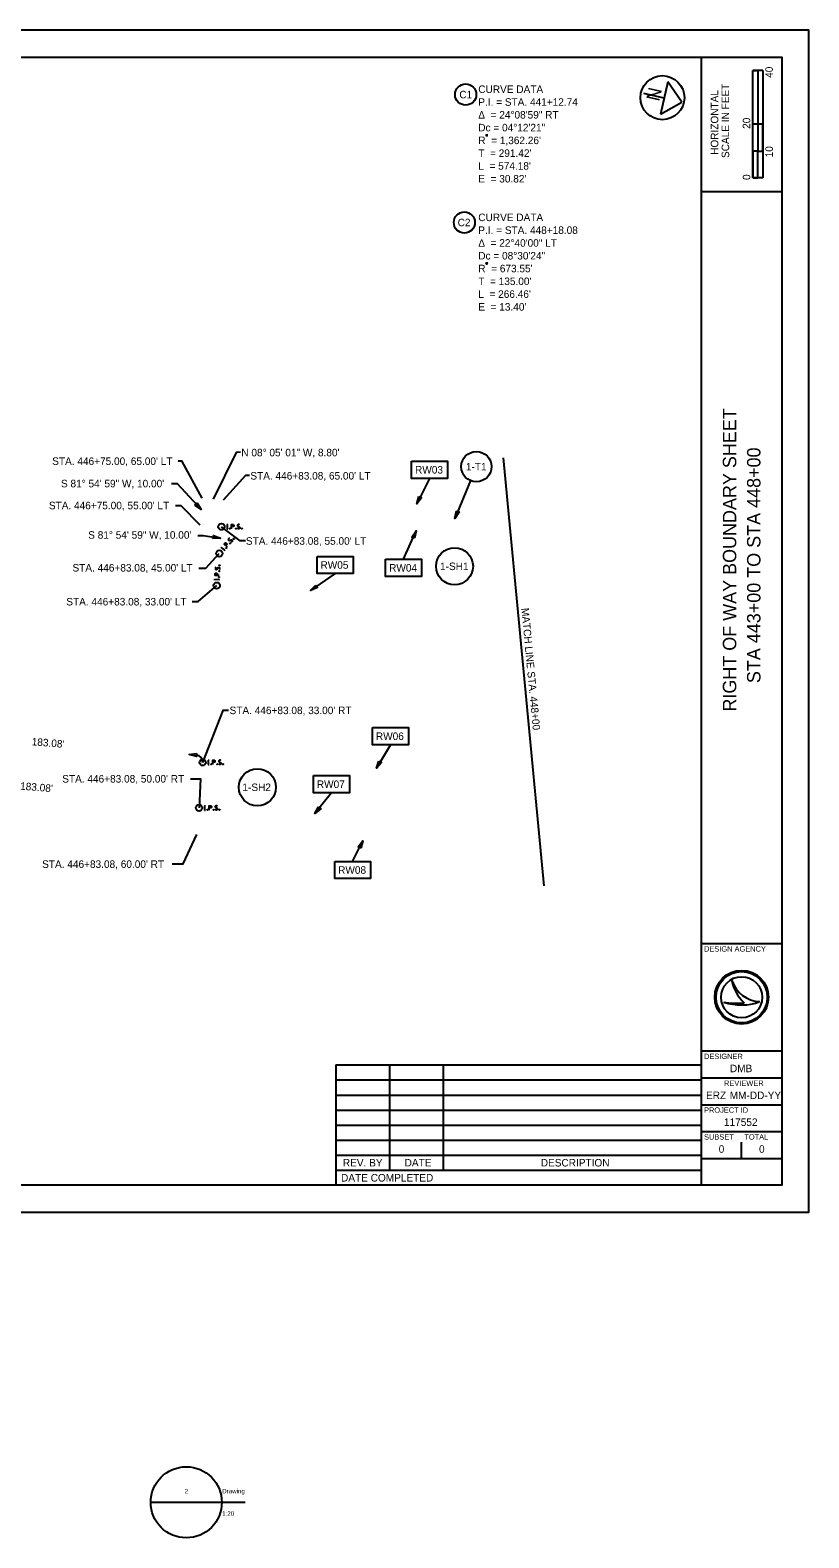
# Model space of a CAD drawing. Extents: x 0 to 1181, y -186 to 440.
# Drawn here: x 390 to 680, y -121 to 440 of the extents above; entities that cross this region are included whole.
import ezdxf

# ---------------------------------------------------------------- set-up
doc = ezdxf.new("R2010")
doc.units = 0
for name, color, linetype in [('RW_X_CL_100_Bearings', 7, 'Continuous'), ('RW_X_CL_100_Curve_Data', 7, 'Continuous'), ('SH_Border', 7, 'Continuous'), ('SH_Cut_Line', 7, 'Continuous'), ('SH_Data', 7, 'Continuous'), ('SH_Masking', 7, 'Continuous'), ('SH_Text', 7, 'Continuous'), ('SV_X_Shot_Marker', 7, 'Continuous')]:
    doc.layers.add(name, color=color, linetype=linetype)

msp = doc.modelspace()

# ---------------------------------------------------------------- linework, layer by layer
at = {"layer": 'RW_X_CL_100_Bearings'}
for points in [[(463.44, 255.96), (463.79, 255.96)], [(463.44, 254.36), (463.79, 254.36)], [(463.62, 254.36), (463.62, 255.96)], [(464.58, 254.57), (464.63, 254.57), (464.66, 254.55), (464.7, 254.5), (464.7, 254.43), (464.66, 254.38), (464.63, 254.36), (464.58, 254.36), (464.54, 254.38), (464.51, 254.43), (464.51, 254.5), (464.54, 254.55), (464.58, 254.57)], [(465.18, 254.36), (465.18, 255.96), (465.71, 255.96), (465.77, 255.94), (465.84, 255.92), (465.88, 255.89), (465.91, 255.87), (465.95, 255.81), (465.99, 255.74), (466.01, 255.64), (466.01, 255.49), (466, 255.44), (465.98, 255.36), (465.93, 255.28), (465.89, 255.24), (465.85, 255.21), (465.8, 255.19), (465.71, 255.18), (465.18, 255.18)], [(466.82, 254.57), (466.88, 254.57), (466.91, 254.55), (466.95, 254.5), (466.95, 254.43), (466.91, 254.38), (466.88, 254.36), (466.82, 254.36), (466.79, 254.38), (466.76, 254.43), (466.76, 254.5), (466.79, 254.55), (466.82, 254.57)], [(468.19, 255.84), (468.17, 255.87), (468.14, 255.89), (468.04, 255.93), (467.92, 255.96), (467.83, 255.96), (467.79, 255.96), (467.65, 255.92), (467.53, 255.84), (467.45, 255.74), (467.43, 255.64), (467.43, 255.57), (467.45, 255.47), (467.54, 255.38), (468.15, 255), (468.2, 254.95), (468.22, 254.9), (468.25, 254.82), (468.25, 254.75), (468.24, 254.67), (468.22, 254.62), (468.2, 254.56), (468.18, 254.51), (468.16, 254.47), (468.12, 254.43), (468.09, 254.41), (468.05, 254.38), (468.01, 254.37), (467.92, 254.36), (467.76, 254.36), (467.66, 254.38), (467.52, 254.47), (467.43, 254.55)], [(469.01, 254.57), (469.06, 254.57), (469.09, 254.55), (469.13, 254.5), (469.13, 254.43), (469.09, 254.38), (469.06, 254.36), (469.01, 254.36), (468.97, 254.38), (468.94, 254.43), (468.94, 254.5), (468.97, 254.55), (469.01, 254.57)], [(461.29, 247.26), (461.52, 247.53)], [(462.64, 246.37), (461.4, 247.39)], [(463.63, 247.58), (462.4, 248.6), (462.73, 249.01), (462.78, 249.04), (462.85, 249.09), (462.89, 249.1), (462.93, 249.11), (463.01, 249.1), (463.08, 249.08), (463.17, 249.04), (463.28, 248.94), (463.32, 248.9), (463.36, 248.84), (463.4, 248.75), (463.4, 248.69), (463.4, 248.65), (463.38, 248.59), (463.34, 248.51), (463, 248.1)], [(463.08, 247.25), (463.12, 247.29), (463.16, 247.3), (463.22, 247.3), (463.27, 247.26), (463.28, 247.2), (463.28, 247.16), (463.25, 247.11), (463.21, 247.11), (463.15, 247.11), (463.1, 247.15), (463.08, 247.21), (463.08, 247.25)], [(464.4, 250.85), (464.37, 250.85), (464.32, 250.84), (464.23, 250.79), (464.14, 250.71), (464.08, 250.64), (464.06, 250.62), (464, 250.48), (463.98, 250.34), (464.01, 250.22), (464.07, 250.14), (464.13, 250.09), (464.22, 250.04), (464.35, 250.05), (465.02, 250.28), (465.1, 250.29), (465.15, 250.28), (465.22, 250.24), (465.28, 250.2), (465.33, 250.14), (465.36, 250.1), (465.4, 250.04), (465.42, 249.99), (465.44, 249.95), (465.45, 249.9), (465.44, 249.86), (465.44, 249.81), (465.42, 249.78), (465.37, 249.69), (465.27, 249.57), (465.19, 249.51), (465.03, 249.46), (464.92, 249.44)], [(464.51, 248.99), (464.55, 249.03), (464.59, 249.04), (464.65, 249.03), (464.7, 248.99), (464.71, 248.93), (464.71, 248.89), (464.68, 248.85), (464.64, 248.84), (464.58, 248.85), (464.53, 248.89), (464.51, 248.95), (464.51, 248.99)], [(465.9, 250.67), (465.93, 250.71), (465.97, 250.72), (466.03, 250.72), (466.08, 250.68), (466.1, 250.62), (466.1, 250.58), (466.06, 250.54), (466.02, 250.53), (465.96, 250.53), (465.92, 250.57), (465.9, 250.63), (465.9, 250.67)], [(462.53, 246.24), (462.75, 246.51)], [(460.63, 236.95), (459.04, 237.02), (459.06, 237.55), (459.07, 237.6), (459.1, 237.68), (459.13, 237.71), (459.16, 237.74), (459.22, 237.78), (459.29, 237.81), (459.39, 237.83), (459.54, 237.82), (459.59, 237.81), (459.66, 237.78), (459.75, 237.74), (459.78, 237.69), (459.81, 237.66), (459.83, 237.6), (459.84, 237.51), (459.82, 236.98)], [(459.28, 240.02), (459.25, 240), (459.23, 239.97), (459.19, 239.87), (459.15, 239.75), (459.15, 239.66), (459.15, 239.63), (459.18, 239.48), (459.25, 239.36), (459.35, 239.28), (459.45, 239.25), (459.52, 239.25), (459.63, 239.26), (459.72, 239.35), (460.12, 239.94), (460.17, 239.99), (460.23, 240.01), (460.3, 240.03), (460.38, 240.03), (460.45, 240.01), (460.5, 240), (460.56, 239.97), (460.61, 239.95), (460.65, 239.93), (460.69, 239.89), (460.71, 239.86), (460.73, 239.81), (460.75, 239.78), (460.75, 239.68), (460.75, 239.52), (460.72, 239.43), (460.62, 239.29), (460.54, 239.2)], [(460.39, 236.35), (460.4, 236.41), (460.42, 236.44), (460.47, 236.47), (460.54, 236.47), (460.59, 236.43), (460.61, 236.4), (460.61, 236.34), (460.58, 236.31), (460.53, 236.28), (460.47, 236.28), (460.42, 236.32), (460.39, 236.35)], [(460.49, 238.6), (460.49, 238.65), (460.52, 238.68), (460.57, 238.72), (460.64, 238.71), (460.68, 238.68), (460.71, 238.64), (460.71, 238.59), (460.68, 238.56), (460.63, 238.53), (460.56, 238.53), (460.52, 238.56), (460.49, 238.6)], [(460.59, 240.78), (460.59, 240.83), (460.62, 240.87), (460.67, 240.9), (460.73, 240.89), (460.78, 240.86), (460.8, 240.82), (460.8, 240.77), (460.77, 240.74), (460.72, 240.71), (460.66, 240.71), (460.61, 240.74), (460.59, 240.78)], [(458.96, 235.28), (458.98, 235.63)], [(460.57, 235.38), (458.97, 235.45)], [(460.56, 235.21), (460.57, 235.56)], [(456.45, 168.24), (456.8, 168.24)], [(456.45, 166.64), (456.8, 166.64)], [(456.63, 166.64), (456.63, 168.24)], [(457.58, 166.85), (457.64, 166.85), (457.67, 166.82), (457.71, 166.77), (457.71, 166.71), (457.67, 166.66), (457.64, 166.64), (457.58, 166.64), (457.55, 166.66), (457.52, 166.71), (457.52, 166.77), (457.55, 166.82), (457.58, 166.85)], [(458.19, 166.64), (458.19, 168.24), (458.72, 168.24), (458.78, 168.22), (458.85, 168.2), (458.89, 168.17), (458.92, 168.15), (458.96, 168.08), (459, 168.02), (459.02, 167.92), (459.02, 167.77), (459.01, 167.72), (458.98, 167.64), (458.94, 167.55), (458.9, 167.52), (458.86, 167.49), (458.81, 167.47), (458.72, 167.45), (458.19, 167.45)], [(459.83, 166.85), (459.89, 166.85), (459.92, 166.82), (459.95, 166.77), (459.95, 166.71), (459.92, 166.66), (459.89, 166.64), (459.83, 166.64), (459.8, 166.66), (459.77, 166.71), (459.77, 166.77), (459.8, 166.82), (459.83, 166.85)], [(461.2, 168.12), (461.18, 168.15), (461.15, 168.17), (461.05, 168.21), (460.92, 168.24), (460.84, 168.24), (460.8, 168.24), (460.66, 168.2), (460.54, 168.12), (460.46, 168.02), (460.44, 167.92), (460.44, 167.84), (460.46, 167.74), (460.55, 167.66), (461.16, 167.28), (461.21, 167.23), (461.23, 167.18), (461.26, 167.1), (461.26, 167.03), (461.24, 166.95), (461.23, 166.9), (461.21, 166.84), (461.19, 166.79), (461.17, 166.75), (461.13, 166.71), (461.1, 166.69), (461.06, 166.66), (461.02, 166.65), (460.92, 166.64), (460.77, 166.64), (460.67, 166.66), (460.53, 166.75), (460.44, 166.82)], [(462.02, 166.85), (462.07, 166.85), (462.1, 166.82), (462.14, 166.77), (462.14, 166.71), (462.1, 166.66), (462.07, 166.64), (462.02, 166.64), (461.98, 166.66), (461.95, 166.71), (461.95, 166.77), (461.98, 166.82), (462.02, 166.85)], [(455.1, 151.29), (455.45, 151.29)], [(455.1, 149.69), (455.45, 149.69)], [(455.28, 149.69), (455.28, 151.29)], [(456.23, 149.9), (456.29, 149.9), (456.32, 149.88), (456.36, 149.83), (456.36, 149.76), (456.32, 149.71), (456.29, 149.69), (456.23, 149.69), (456.2, 149.71), (456.17, 149.76), (456.17, 149.83), (456.2, 149.88), (456.23, 149.9)], [(456.84, 149.69), (456.84, 151.29), (457.37, 151.29), (457.42, 151.28), (457.5, 151.25), (457.54, 151.23), (457.57, 151.2), (457.61, 151.14), (457.65, 151.07), (457.67, 150.97), (457.67, 150.82), (457.66, 150.77), (457.63, 150.7), (457.59, 150.61), (457.55, 150.57), (457.51, 150.55), (457.46, 150.52), (457.37, 150.51), (456.84, 150.51)], [(458.48, 149.9), (458.54, 149.9), (458.57, 149.88), (458.6, 149.83), (458.6, 149.76), (458.57, 149.71), (458.54, 149.69), (458.48, 149.69), (458.45, 149.71), (458.42, 149.76), (458.42, 149.83), (458.45, 149.88), (458.48, 149.9)], [(459.85, 151.18), (459.83, 151.2), (459.79, 151.23), (459.7, 151.26), (459.57, 151.29), (459.49, 151.29), (459.45, 151.29), (459.31, 151.25), (459.19, 151.18), (459.11, 151.07), (459.09, 150.97), (459.09, 150.9), (459.11, 150.8), (459.2, 150.71), (459.81, 150.33), (459.86, 150.28), (459.88, 150.23), (459.9, 150.16), (459.9, 150.08), (459.89, 150), (459.88, 149.95), (459.86, 149.89), (459.84, 149.84), (459.82, 149.8), (459.78, 149.76), (459.75, 149.74), (459.71, 149.71), (459.67, 149.7), (459.57, 149.69), (459.42, 149.69), (459.32, 149.71), (459.18, 149.8), (459.09, 149.88)], [(460.67, 149.9), (460.72, 149.9), (460.75, 149.88), (460.79, 149.83), (460.79, 149.76), (460.75, 149.71), (460.72, 149.69), (460.67, 149.69), (460.63, 149.71), (460.6, 149.76), (460.6, 149.83), (460.63, 149.88), (460.67, 149.9)]]:
    msp.add_lwpolyline(points, dxfattribs=at)
for centre in [(461.42, 255.16), (460.63, 245.19), (459.67, 233.23), (454.43, 167.43), (453.08, 150.49)]:
    msp.add_circle(centre, 1.2, dxfattribs=at)
at = {"layer": 'SH_Border'}
for p, q in [((640, 10), (640, 430)), ((640, 380), (670, 380)), ((640, 100), (670, 100)), ((640, 60), (670, 60)), ((640, 50), (670, 50)), ((640, 40), (670, 40)), ((640, 30), (670, 30)), ((640, 20), (670, 20))]:
    msp.add_line(p, q, dxfattribs=at)
msp.add_lwpolyline([(30, 430), (670, 430), (670, 10), (30, 10)], close=True, dxfattribs=at)
at = {"layer": 'SH_Cut_Line'}
msp.add_lwpolyline([(0, 0), (680, 0), (680, 440), (0, 440)], close=True, dxfattribs=at)
at = {"layer": 'SH_Data'}
for p, q in [((659.13, 385), (659.13, 425)), ((662.88, 425), (659.13, 425)), ((659.13, 405), (659.13, 425)), ((659.13, 425), (661, 425)), ((661, 425), (661.02, 425)), ((661.02, 425), (661.02, 405)), ((662.88, 425), (662.88, 385)), ((661.02, 405), (659.13, 405)), ((662.87, 405), (661, 405)), ((661, 405), (661, 395)), ((662.87, 395), (662.87, 405)), ((661, 395), (659.13, 395)), ((659.13, 395), (659.13, 385)), ((661, 385), (661, 395)), ((661, 395), (662.87, 395)), ((662.88, 385), (659.13, 385)), ((659.13, 385), (661, 385)), ((566.31, 280.82), (581.34, 121.53)), ((651.35, 86.19), (651.35, 86.19)), ((655, 80), (655, 80)), ((648.34, 78.19), (648.34, 78.19)), ((661.75, 78.37), (661.75, 78.37)), ((655, 20), (655, 26)), ((435.11, -108.01), (461.56, -108.01)), ((448.45, -108.01), (470.24, -108.01))]:
    msp.add_line(p, q, dxfattribs=at)
for centre, radius in [((655, 80), 10), ((655, 80), 9.54), ((655, 80), 9.54), ((655, 80), 7.64), ((448.33, -108.01), 13.23)]:
    msp.add_circle(centre, radius, dxfattribs=at)
for centre, radius, start, end in [((662.32, 89.95), 11.6, 198.9257, 198.9319), ((666.93, 89.4), 15.91, 191.6379, 191.6421), ((662.32, 89.95), 11.6, 198.9319, 267.1657), ((666.93, 89.4), 15.91, 191.6421, 226.0947), ((654.79, 97.4), 20.26, 251.4576, 290.0832), ((652.96, 103.09), 25.32, 259.4964, 259.4995), ((654.79, 97.4), 20.26, 251.4527, 251.4576), ((652.96, 103.09), 25.32, 259.4995, 276.6672)]:
    msp.add_arc(centre, radius, start, end, dxfattribs=at)
at = {"layer": 'SH_Masking'}
msp.add_circle((625.5, 414.86), 8.2, dxfattribs=at)
at = {"layer": 'SH_Text'}
for p, q in [((626.14, 414.71), (618.59, 416.41)), ((627.48, 420.72), (624.79, 408.71)), ((632.8, 413.22), (627.48, 420.72)), ((624.79, 408.71), (632.8, 413.22)), ((538.86, 273.14), (534.08, 263.66)), ((554.11, 272.3), (548.27, 258.27)), ((529.19, 243.05), (533.87, 253.64)), ((503.7, 237.7), (494.52, 231.4)), ((524.32, 173.97), (519.07, 165.25)), ((502.4, 156.1), (496.21, 148.34)), ((510.25, 130.56), (514.06, 138.21)), ((503.93, 54.8), (503.93, 10)), ((503.93, 54.8), (640, 54.8)), ((523.93, 54.8), (523.93, 15.6)), ((543.93, 54.8), (543.93, 15.6)), ((503.93, 49.2), (640, 49.2)), ((503.93, 43.6), (640, 43.6)), ((503.93, 38), (640, 38)), ((503.93, 32.4), (640, 32.4)), ((503.93, 26.8), (640, 26.8)), ((503.93, 21.2), (640, 21.2)), ((503.93, 15.6), (640, 15.6)), ((640, 10), (640, 10))]:
    msp.add_line(p, q, dxfattribs=at)
for points in [[(468.48, 282.85), (466.86, 282.84), (458.32, 265.43)], [(445.31, 279.72), (446.62, 279.72), (454.16, 265.77)], [(442.81, 271.18), (444.95, 271.18), (453.82, 261.53)], [(462.22, 265.12), (470.46, 274.3), (471.92, 274.3)], [(444.36, 263.03), (446.25, 263.03), (453.37, 255.8)], [(470.37, 249.87), (468.35, 249.87), (461.42, 255.16)], [(452.62, 251.92), (454.61, 251.92), (461.08, 250.84)], [(453.07, 239.67), (455.65, 239.69), (460.63, 245.19)], [(450.58, 227.34), (452.76, 227.34), (459.67, 233.23)], [(464.01, 186.78), (461.9, 186.78), (454.43, 167.43)], [(449.91, 161.26), (453.67, 161.26), (453.08, 150.49)], [(443.07, 129.69), (447.24, 129.65), (452.29, 140.52)]]:
    msp.add_lwpolyline(points, dxfattribs=at)
for points in [[(532.18, 279.55), (545.54, 279.55), (545.54, 273.14), (532.18, 273.14)], [(451.52, 263.21), (452.34, 263.97), (453.82, 261.53)], [(534.84, 266.41), (535.84, 265.91), (534.08, 263.66)], [(548.83, 261.07), (549.86, 260.64), (548.27, 258.27)], [(533.25, 250.85), (532.22, 251.3), (533.87, 253.64)], [(458.22, 250.75), (458.41, 251.85), (461.08, 250.84)], [(497.02, 244.11), (510.38, 244.11), (510.38, 237.7), (497.02, 237.7)], [(522.51, 243.05), (535.87, 243.05), (535.87, 236.64), (522.51, 236.64)], [(496.52, 233.45), (497.15, 232.53), (494.52, 231.4)], [(517.64, 180.38), (531, 180.38), (531, 173.97), (517.64, 173.97)], [(452.18, 170.68), (452.09, 169.57), (449.35, 170.35)], [(520.04, 167.94), (521, 167.36), (519.07, 165.25)], [(495.72, 162.5), (509.08, 162.5), (509.08, 156.1), (495.72, 156.1)], [(497.52, 150.88), (498.39, 150.18), (496.21, 148.34)], [(513.31, 135.45), (512.31, 135.95), (514.06, 138.21)], [(503.57, 130.56), (516.93, 130.56), (516.93, 124.16), (503.57, 124.16)]]:
    msp.add_lwpolyline(points, close=True, dxfattribs=at)
for centre, radius in [((625.5, 414.86), 8.2), ((552.3, 416.02), 3.94), ((551.82, 368.39), 3.94), ((556.28, 277.51), 5.65), ((548.16, 240.41), 6.88), ((474.78, 158.15), 6.88)]:
    msp.add_circle(centre, radius, dxfattribs=at)
msp.add_arc((451.94, 167.63), 2.5, 355.4436, 85.4436, dxfattribs=at)
at = {"layer": 'SV_X_Shot_Marker'}
for p, q in [((560.61, 400.74), (559.63, 400.96)), ((560.23, 401.34), (560.01, 400.36)), ((560.12, 400.85), (560.12, 400.85)), ((560.23, 353.64), (560.01, 352.66)), ((560.61, 353.04), (559.63, 353.26)), ((560.12, 353.15), (560.12, 353.15))]:
    msp.add_line(p, q, dxfattribs=at)

# ---------------------------------------------------------------- texts
at = {"layer": 'RW_X_CL_100_Curve_Data'}
for s, p in [('CURVE DATA', (557, 416.61)), ('CURVE DATA', (557, 416.61)), ('Δ  = 24°08\'59" RT', (557, 407.09)), ('Δ  = 24°08\'59" RT', (557, 407.09)), ('P.I. = STA. 441+12.74', (557, 411.85)), ('P.I. = STA. 441+12.74', (557, 411.85)), ('Dc = 04°12\'21"', (557, 402.33)), ('Dc = 04°12\'21"', (557, 402.33)), ("R  = 1,362.26'", (557, 397.57)), ("R  = 1,362.26'", (557, 397.57)), ("T  = 291.42'", (557, 392.81)), ("T  = 291.42'", (557, 392.81)), ("L  = 574.18'", (557, 388.05)), ("L  = 574.18'", (557, 388.05)), ("E  = 30.82'", (557, 383.29)), ("E  = 30.82'", (557, 383.29)), ('CURVE DATA', (557, 368.91)), ('CURVE DATA', (557, 368.91)), ('P.I. = STA. 448+18.08', (557, 364.15)), ('P.I. = STA. 448+18.08', (557, 364.15)), ('Δ  = 22°40\'00" LT', (557, 359.39)), ('Δ  = 22°40\'00" LT', (557, 359.39)), ('Dc = 08°30\'24"', (557, 354.63)), ('Dc = 08°30\'24"', (557, 354.63)), ("R  = 673.55'", (557, 349.87)), ("R  = 673.55'", (557, 349.87)), ("T  = 135.00'", (557, 345.11)), ("T  = 135.00'", (557, 345.11)), ("L  = 266.46'", (557, 340.35)), ("L  = 266.46'", (557, 340.35)), ("E  = 13.40'", (557, 335.59)), ("E  = 13.40'", (557, 335.59))]:
    msp.add_text(s, height=2.8, dxfattribs=at).set_placement(p)
at = {"layer": 'SH_Data'}
for s, height, rotation, p in [('40', 2.8, 90, (666.61, 422.25)), ('HORIZONTAL', 2.8, 90, (646.3, 393.58)), ('SCALE IN FEET', 2.8, 90, (650.35, 392.41)), ('20', 2.8, 90, (658.21, 403.25)), ('10', 2.8, 90, (666.61, 392.65)), ('0', 2.8, 90, (658.21, 384.23)), ('RIGHT OF WAY BOUNDARY SHEET', 5, 90, (653, 186.33)), ('STA 443+00 TO STA 448+00', 5, 90, (662, 196.93)), ('MATCH LINE STA. 448+00', 2.8, 275.3895, (573, 224.79))]:
    msp.add_text(s, height=height, rotation=rotation, dxfattribs=at).set_placement(p)
for s, height, p in [('DESIGN AGENCY', 2, (641, 97)), ('DESIGNER', 2, (641, 57)), ('DMB', 2.8, (650.65, 52.1)), ('ERZ', 2.8, (641.74, 42.1)), ('REVIEWER', 2, (648.44, 47)), ('MM-DD-YY', 2.8, (650.55, 42.1)), ('PROJECT ID', 2, (641, 37)), ('117552', 2.8, (648.42, 32.1)), ('SUBSET', 2, (641, 27)), ('TOTAL', 2, (656, 27)), ('0', 2.8, (646.46, 22.1)), ('0', 2.8, (661.46, 22.1)), ('2', 1.67, (447.75, -104.68)), ('Drawing', 1.667, (461.69, -104.68)), ('1:20', 1.667, (461.69, -113.01))]:
    msp.add_text(s, height=height, dxfattribs=at).set_placement(p)
at = {"layer": 'SH_Text'}
for s, p in [('C1', (549.95, 414.62)), ('C2', (549.31, 366.99)), ("STA. 446+75.00, 65.00' LT", (398.45, 278.15)), ('N 08° 05\' 01" W, 8.80\'', (468.82, 281.36)), ("STA. 446+83.08, 65.00' LT", (472.18, 272.71)), ('RW03', (533.46, 274.95)), ('1-T1', (552.41, 276.11)), ('S 81° 54\' 59" W, 10.00\'', (401.71, 269.82)), ("STA. 446+75.00, 55.00' LT", (397.21, 261.65)), ('S 81° 54\' 59" W, 10.00\'', (411.84, 250.68)), ("STA. 446+83.08, 55.00' LT", (470.53, 248.44)), ('RW05', (498.27, 239.51)), ('1-SH1', (542.77, 239.01)), ("STA. 446+83.08, 45.00' LT", (405.99, 238.47)), ('RW04', (523.82, 238.45)), ("STA. 446+83.08, 33.00' LT", (403.69, 225.84)), ("STA. 446+83.08, 33.00' RT", (464.45, 185.39)), ('RW06', (518.9, 175.77)), ("STA. 446+83.08, 50.00' RT", (402.18, 159.91)), ('1-SH2', (469.22, 156.75)), ('RW07', (496.92, 157.9)), ("STA. 446+83.08, 60.00' RT", (394.71, 128.15)), ('RW08', (504.84, 125.96)), ('REV. BY', (506.61, 17)), ('DATE', (529.59, 17)), ('DESCRIPTION', (580.25, 17)), ('DATE COMPLETED', (505.93, 11.4))]:
    msp.add_text(s, height=2.8, dxfattribs=at).set_placement(p)
for s, height, rotation, p in [('N', 5, 257.36, (620.48, 419.08)), ("183.08'", 2.8, 355.4436, (390.73, 173.8)), ("183.08'", 2.8, 355.4436, (386.42, 157.29))]:
    msp.add_text(s, height=height, rotation=rotation, dxfattribs=at).set_placement(p)

doc.saveas('drawing.dxf')
